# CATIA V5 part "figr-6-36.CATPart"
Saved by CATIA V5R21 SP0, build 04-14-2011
Part number: Part1
Bounding box of the stored display mesh (mm): x -40.3 to 40.3, y -45.975 to 45.975, z 0 to 40
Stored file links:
  D:\CATIA V5R21 E-RESOURCES\CATIA-V5R21\catia-v5r21-prt\c06-catia-v5r21-prt\c06-catia-v5r21-figr-6-36.CATPart
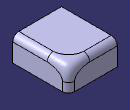
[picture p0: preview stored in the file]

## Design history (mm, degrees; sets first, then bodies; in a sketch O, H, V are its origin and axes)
Body1 (main body)
  Sketch1 on xy-plane, origin (0, 0, 0), H (1, 0, 0), V (0, 1, 0)
    line L1 (-40.2998, 45.9753) -> (40.2998, 45.9753)
    line L2 (40.2998, 45.9753) -> (40.2998, -45.9753)
    line L3 (40.2998, -45.9753) -> (-40.2998, -45.9753)
    line L4 (-40.2998, -45.9753) -> (-40.2998, 45.9753)
    axis line L5 (40.2998, -45.9753) -> (-40.2998, 45.9753)
    horizontal: L1 H, L3 H
    vertical: L2 V, L4 V
    midpoint: O L5
  Pad1: profile Sketch1, direction (0, 0, 1), length 40
  Fillet1: radius 10, on edge [face of Pad1 | face of Pad1] (x3)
